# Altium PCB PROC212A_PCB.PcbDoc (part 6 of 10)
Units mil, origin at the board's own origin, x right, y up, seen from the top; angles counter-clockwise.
Board outline 3032.48 x 3598.78 mil, 4 copper layers (Top Layer, L2_GND1, L3_PWR1, Bottom Layer), stack 60.58 mil thick; 432 components, 310 nets, 7775 pads, 1236 vias.
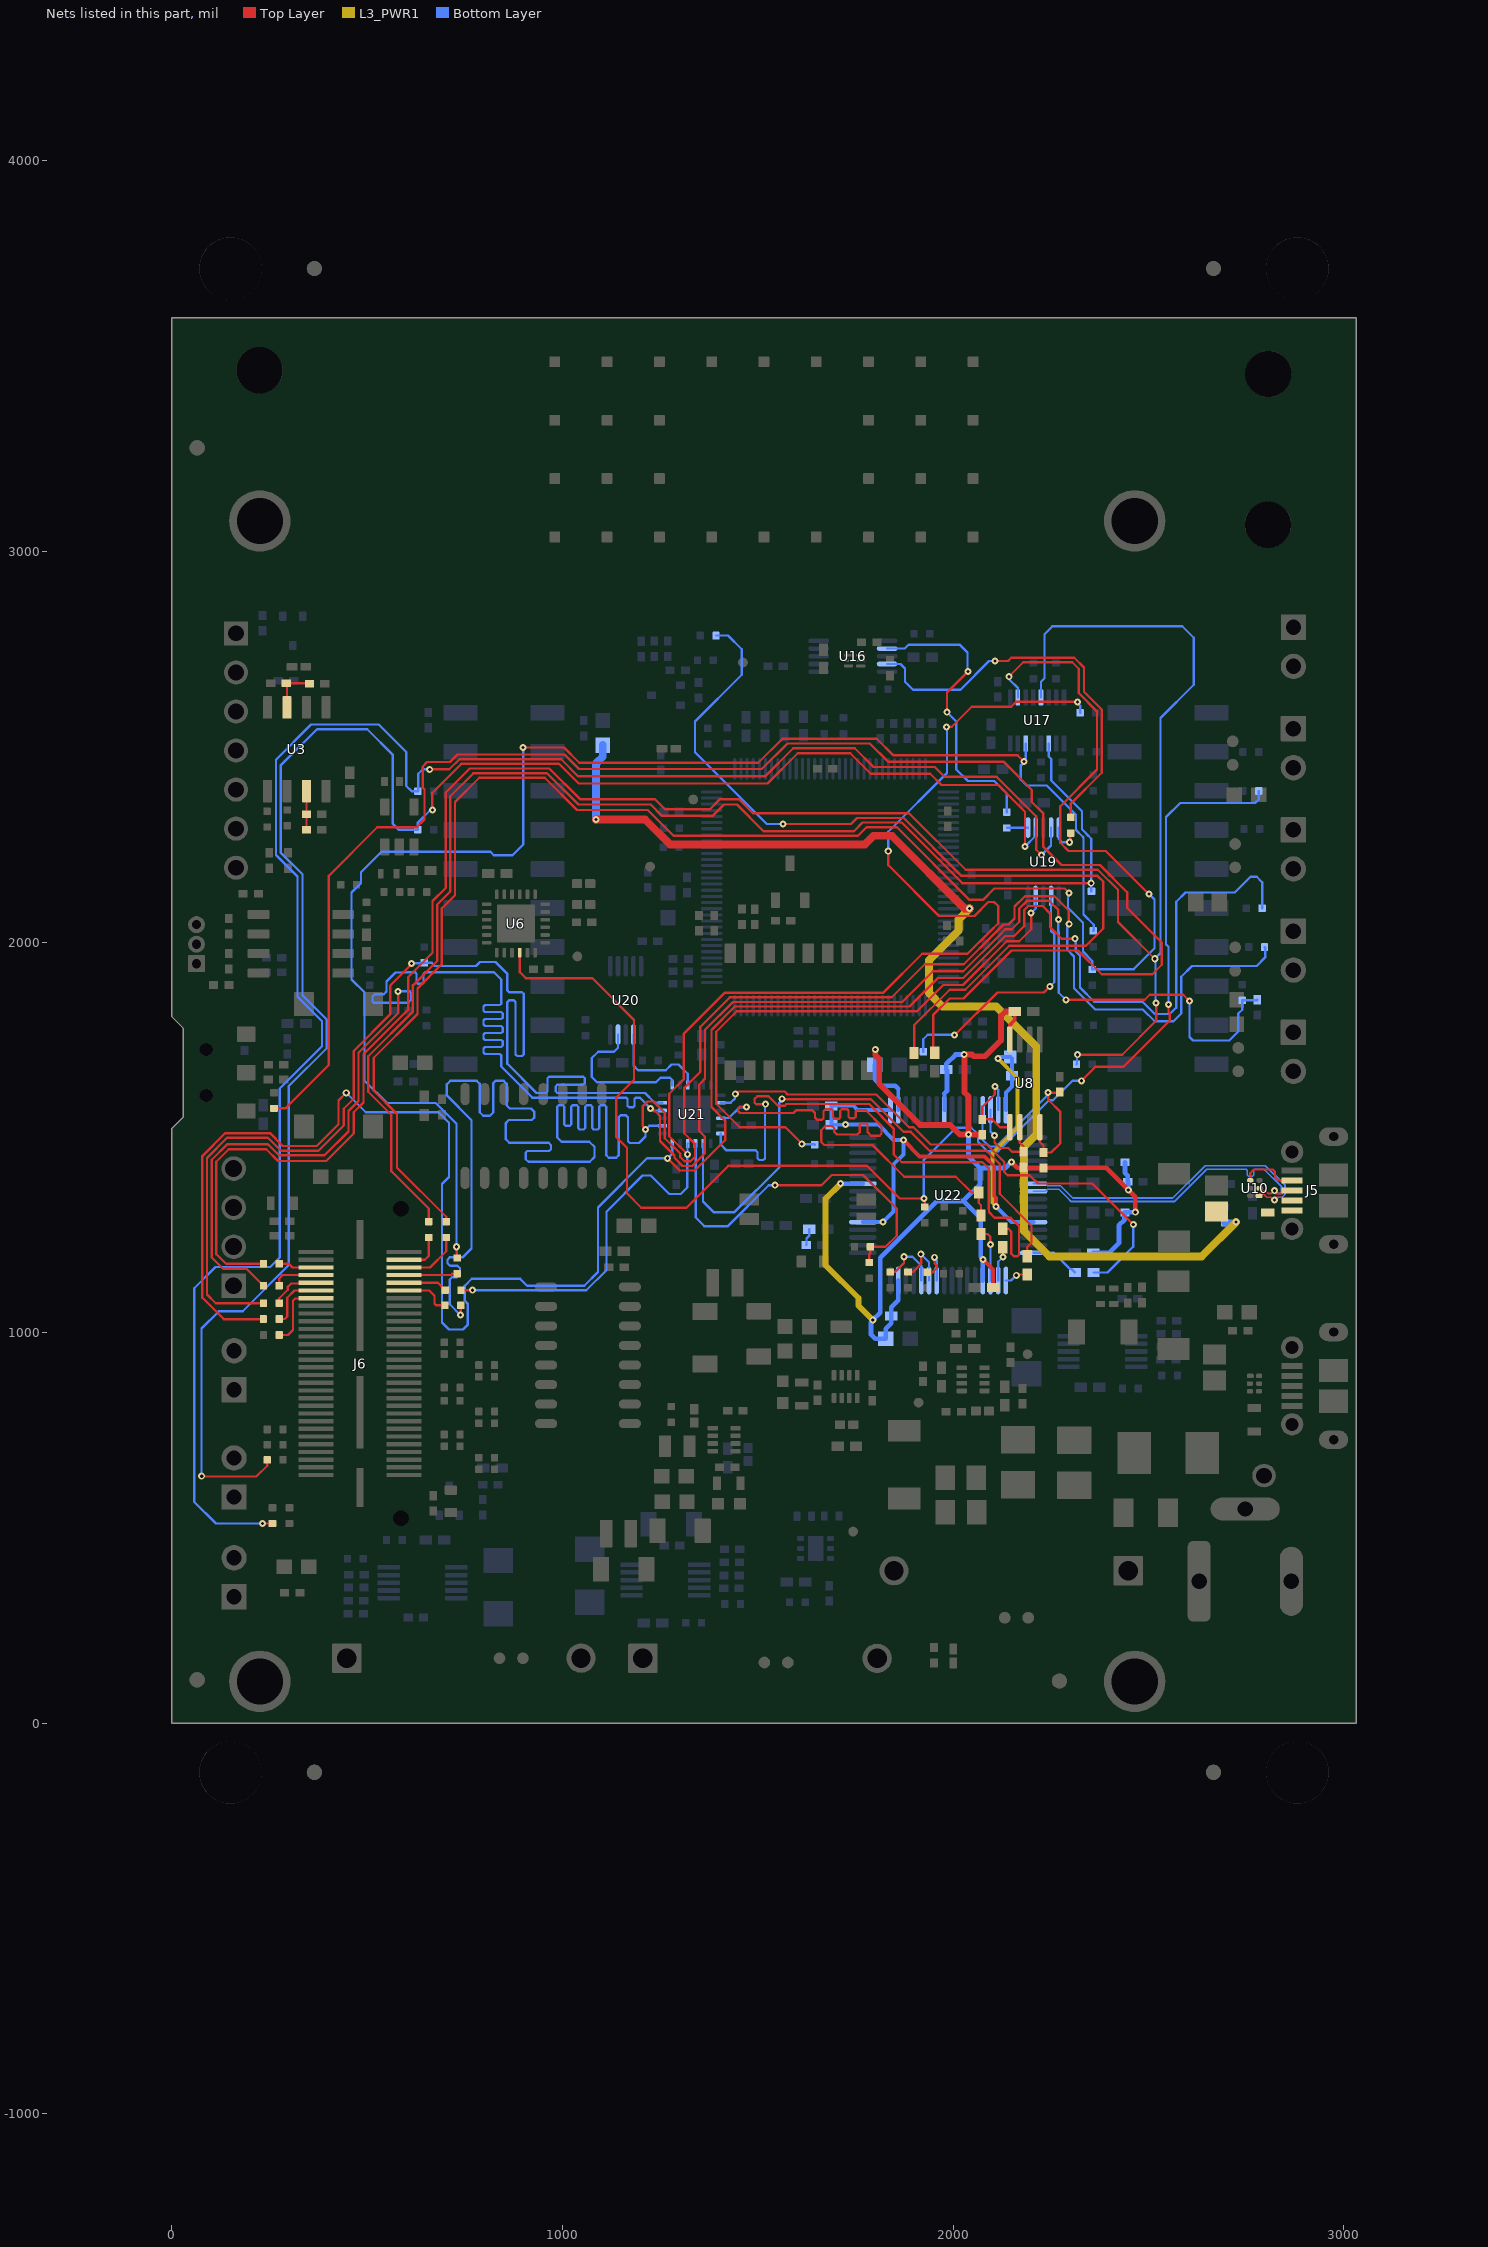
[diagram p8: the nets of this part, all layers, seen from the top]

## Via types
v1: diameter 18, hole 8, Top Layer to Bottom Layer, tented both sides, 1224 vias
v2: diameter 19.68, hole 7.87, Top Layer to Bottom Layer, tented both sides, 10 vias
v3: diameter 19.68, hole 7.87, Top Layer to Bottom Layer, 2 vias

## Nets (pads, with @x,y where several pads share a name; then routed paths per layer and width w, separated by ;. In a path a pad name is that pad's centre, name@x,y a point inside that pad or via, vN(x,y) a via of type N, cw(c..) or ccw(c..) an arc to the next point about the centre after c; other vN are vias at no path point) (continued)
DC_PWM_AUTO_CTRL_GPIO: R40.2 R133.2 U6.16 | length 3484.4
  Top Layer w5.9: U6.16@890.43,1972.62 890.43,1923.12 906.27,1907.27 1076.45,1907.27 1182.87,1800.85 1182.87,1647.28 1137.43,1601.84 1137.43,1500.83 1164.88,1473.38 1164.88,1356.67 1201.55,1319.99 1317.16,1319.99 1424.72,1427.55 1779.55,1427.55 1863.58,1343.52 v1(1925.22,1343.52) 1927.81,1340.93 R40.2@1927.81,1321.6 ; v1(2328.66,1644.86) 2364.23,1680.43 2435.65,1680.43 2555.07,1799.85 2555.07,1818 2551.72,1821.35 v1(2551.72,1840.29)
  Bottom Layer w5.9: v1(1925.22,1343.52) 1925.22,1442.48 2007.64,1524.91 2046.8,1524.91 2063.6,1508.11 2063.6,1489.01 2087.87,1464.74 2115.52,1464.74 2245.63,1594.84 2255.54,1594.84 2305.56,1644.86 v1(2328.66,1644.86) ; v1(2551.72,1840.29) 2551.44,1840.56 2551.44,1988.1 2545.39,1994.15 2545.39,2320.09 2581.4,2356.09 2773.14,2356.09 2782.37,2365.32 R133.2@2782.37,2387.08
DCA_INT: J6.10 R57.1 | length 113.3
  Top Layer w5.9: J6.10@594.31,1127.69 681.28,1127.69 688.86,1120.1 688.86,1119.73 R57.1@699.67,1108.93
DCA_LP_FTDI_SPI_CLK: U20.9 U21.1 | length 392.1
  Bottom Layer w5.9: U20.9@1142.17,1763.23 1142.17,1729.73 1131.77,1719.33 1091.42,1719.33 1075.14,1703.06 1075.14,1654.33 1088.21,1641.25 1216.33,1641.25 1239.62,1641.25 1251.36,1653 1274.7,1653 1281.34,1646.36 U21.1@1281.34,1633.76
DCA_LP_FTDI_SPI_CS: U20.7 U21.3 | length 268.5
  Bottom Layer w5.9: U20.7@1181.54,1763.23 1181.54,1683.86 1193.31,1672.09 1264.29,1672.09 1278.96,1686.77 1296.84,1686.77 1320.71,1662.9 U21.3@1320.71,1633.76
DCA_LP_HOST_INTR_1: R57.2 R111.1 U21.16 | length 3400.9
  Top Layer w5.9: R57.2@740.02,1108.93 769.6,1108.93 v1(769.83,1108.69) ; v1(1319.73,1456.7) 1273.57,1502.86 1273.57,1611.61 1310.04,1648.08 1310.04,1764.52 1416.16,1870.64 1821.85,1870.64 1921.11,1969.89 2037.16,1969.89 2094.21,2026.94 ; v1(1834.06,2232.66) 1834.06,2197.07 1964.13,2067.01 2054.52,2067.01 2090.25,2102.74 2105.12,2102.74 2115.64,2092.23 2115.64,2048.41 2094.21,2026.98 ; v1(1983.31,2551.09) 1983.53,2551.32 1996.53,2551.32 2047.8,2602.58 2149,2602.58 2162.1,2615.68 2317.57,2615.68 v1(2318.53,2614.72)
  Bottom Layer w5.9: v1@770.2,1108.32 1060.75,1108.32 1112.41,1159.99 1112.41,1309.49 1205.12,1402.2 1225.96,1402.2 1273.23,1354.93 1302.48,1354.93 1319.73,1372.18 v1(1319.73,1456.7) 1320.22,1457.19 1320.22,1483.67 U21.16@1320.71,1484.16 ; v1(1834.06,2232.66) 1834.06,2282.68 1984.31,2432.93 1984.31,2550.09 v1(1983.31,2551.09) ; v1(2318.53,2614.72) 2318.53,2611.99 2325.3,2605.23 R111.1@2325.3,2587.21
DCA_LP_SPI_CLK: R58.1 R151.1 U21.23 | length 2907.6
  Top Layer w5.9: R58.1@233.98,1075.22 111.97,1075.22 89.83,1097.36 89.83,1447.53 141.25,1498.95 245.96,1498.95 279,1465.91 375.42,1465.91 439.73,1530.21 439.73,1573.52 465.31,1599.09 465.31,1721.09 558.6,1814.38 558.6,1888.34 613.69,1943.43 v1(613.69,1944.72)
  Bottom Layer w5.9: v1(613.69,1944.72) 614.78,1945.81 644.66,1945.81 R151.1@645.75,1946.9 664.83,1946.9 672.93,1938.79 778.53,1938.79 788.55,1948.81 828.72,1948.81 858.89,1918.64 858.89,1878.83 858.89,1875.88 863.07,1871.7 896.51,1871.7 900.69,1867.52 900.69,1712.39 896.51,1708.21 883.97,1708.21 879.79,1712.39 879.79,1846.62 875.61,1850.8 863.07,1850.8 858.89,1846.62 858.89,1705.26 858.89,1688.33 933.51,1613.7 954.47,1613.7 957.42,1613.7 961.6,1617.88 961.6,1651.32 965.78,1655.5 1052.55,1655.5 1056.73,1651.32 1056.73,1638.78 1052.55,1634.6 986.68,1634.6 982.5,1630.42 982.5,1617.88 986.68,1613.7 1054.47,1613.7 1065.78,1613.7 1210.95,1613.7 1236.17,1588.49 U21.23@1255.75,1588.49
DCA_LP_SPI_CS: R56.1 R158.2 R159.1 U21.22 | length 5473.6
  Top Layer w5.9: R56.1@234.25,1120.2 190.75,1163.7 130.75,1163.7 101.73,1192.72 101.73,1442.6 141.19,1482.05 245.44,1482.05 246.04,1481.46 246.62,1481.46 274.07,1454.01 390.83,1454.01 451.95,1515.12 451.95,1567.73 477.45,1593.24 477.45,1716.41 579.27,1818.23 v1(579.27,1873.83) ; v1(1225.25,1574.11) 1227.35,1574.11 1234.43,1567.03 1237.63,1567.03 1249.77,1554.89 1249.77,1490.62 1286.54,1453.85 1286.54,1447.68 1307.37,1426.85 1332.47,1426.85 1364.31,1458.68 1364.31,1502.09 1349.95,1516.45 1349.95,1635.42 1365.03,1650.51 1365.03,1775.58 1436.29,1846.84 1870.05,1846.84 1948.31,1925.09 2026.02,1925.09 2118.01,2017.08 ; 2118.01,2017.12 2133.87,2032.99 2150.2,2032.99 2169.37,2052.15 2169.37,2085.89 2189,2105.52 2246.02,2105.52 2269.66,2081.88 v1(2269.66,2057.65) ; v1(2289.28,1852.25) 2490.5,1852.25 2503.67,1865.42 2589.22,1865.42 v1(2605.24,1849.4)
  Bottom Layer w5.9: v1(579.27,1873.83) 608.68,1873.83 612.91,1869.6 612.91,1852.47 605.15,1844.71 516.88,1844.71 513.43,1848.16 513.43,1860.56 519.21,1866.34 542.04,1866.34 549.44,1873.75 549.44,1899.39 572.36,1922.31 601.72,1922.31 ; 601.88,1922.15 602.35,1922.62 622.73,1922.62 626.31,1919.04 626.31,1896.6 629.89,1893.02 640.63,1893.02 644.21,1896.6 644.21,1919.04 647.79,1922.62 665.85,1922.62 824.65,1922.62 842.94,1904.33 842.94,1863.24 842.94,1842.38 839.36,1838.8 801.39,1838.8 797.81,1835.22 797.81,1824.48 801.39,1820.9 843.41,1820.9 846.99,1817.32 846.99,1806.58 843.41,1803 801.39,1803 797.81,1799.42 797.81,1788.68 801.39,1785.1 843.41,1785.1 846.99,1781.52 846.99,1770.78 843.41,1767.2 801.39,1767.2 797.81,1763.62 797.81,1752.88 801.39,1749.3 843.41,1749.3 846.99,1745.72 846.99,1734.98 843.41,1731.4 801.39,1731.4 797.81,1727.82 797.81,1717.08 801.39,1713.5 839.36,1713.5 842.94,1709.92 842.94,1701.69 842.94,1681.45 922.58,1601.8 1128.52,1601.8 1162.84,1601.8 1166.42,1598.22 1166.42,1580.64 1170,1577.06 1180.74,1577.06 1184.32,1580.64 1184.32,1598.22 1187.9,1601.8 1190.85,1601.8 1197.55,1601.8 v1(1225.25,1574.11) 1228.52,1574.11 1233.83,1568.8 U21.22@1255.75,1568.8 ; v1(2269.66,2057.65) 2269.66,2026.46 2270.74,2025.38 2270.74,1870.31 v1@2288.8,1852.25 ; v1(2605.24,1849.4) 2605.24,1757.16 2614.31,1748.09 2707.31,1748.09 2730.31,1771.09 2730.31,1817.09 2740.23,1827.01 R158.2@2740.23,1850.76 2776.78,1850.76 R159.1@2778.51,1852.49
DCA_LP_SPI_MISO: R59.2 R150.2 U21.20 | length 5535.5
  Top Layer w5.9: v1(739.08,1044.76) 739.28,1044.96 739.28,1069.66 R59.2@739.48,1069.85 ; v1(1212.69,1520.18) 1212.69,1522.45 1205.7,1529.45 1205.7,1579.6 1207.3,1581.2 1207.3,1581.54 1217.81,1592.06 1233.07,1592.06 1261.67,1563.45 1261.67,1497.93 1301.78,1457.82 1301.78,1449.26 1312.3,1438.75 1327.54,1438.75 1339.31,1450.51 1339.31,1483.25 1311.76,1510.8 1311.76,1626.71 1352.6,1667.55 1352.6,1782.85 1428.49,1858.74 1842.95,1858.74 1927.31,1943.09 2027.19,1943.09 2106.11,2022.01 ; 2106.11,2022.05 2128.94,2044.89 2142.1,2044.89 2157.47,2060.25 2157.47,2090.82 2184.07,2117.42 2259.65,2117.42 2296.56,2080.51 2296.56,2047.33 v1(2297.3,2046.59)
  Bottom Layer w5.9: v1(739.08,1044.76) 711.31,1072.54 711.31,1136.09 716.96,1141.75 729.02,1141.75 737.7,1150.42 737.7,1164.7 731.08,1171.31 711.81,1171.31 705.56,1177.57 705.56,1186.73 712.25,1193.43 745.2,1193.43 767.01,1215.23 767.01,1543.98 703.96,1607.03 703.96,1636.2 712.43,1644.67 780.57,1644.67 788.31,1636.94 788.31,1564.2 797.04,1555.48 814.48,1555.48 822.53,1563.52 822.53,1638.87 828.33,1644.67 849.69,1644.67 856.9,1637.47 856.9,1581.96 864.76,1574.1 919.36,1574.1 927.34,1566.12 927.34,1550.46 921.25,1544.37 862.51,1544.37 855.03,1536.89 855.03,1495 863.87,1486.15 964.5,1486.15 970.55,1480.11 970.55,1469.8 965.74,1464.99 909.96,1464.99 905.9,1460.93 905.9,1444.13 912.71,1437.31 1069.79,1437.31 1081.89,1449.41 1081.89,1475.73 1068.59,1489.04 997.24,1489.04 986.52,1499.76 986.52,1541.93 986.52,1578.64 990.1,1582.22 1000.84,1582.22 1004.42,1578.64 1004.42,1533.34 1008,1529.76 1018.74,1529.76 1022.32,1533.34 1022.32,1578.64 1025.9,1582.22 1036.64,1582.22 1040.22,1578.64 1040.22,1523.93 1043.8,1520.35 1054.54,1520.35 1058.12,1523.93 1058.12,1578.64 1061.7,1582.22 1072.44,1582.22 1076.02,1578.64 1076.02,1523.93 1079.6,1520.35 1090.34,1520.35 1093.92,1523.93 1093.92,1578.64 1097.5,1582.22 1108.24,1582.22 1111.82,1578.64 1111.82,1541.93 1111.82,1454.61 1118.66,1447.77 1137.8,1447.77 1143.64,1453.61 1143.64,1551.49 1148.43,1556.28 1162.49,1556.28 1167.77,1551 1167.77,1490.33 1172.33,1485.77 1196.19,1485.77 1212.69,1502.28 v1(1212.69,1520.18) 1221.95,1529.43 U21.20@1255.75,1529.43 ; v1(2297.3,2046.59) 2297.3,2043.31 2292.41,2038.43 2292.41,1980.53 2309.77,1963.18 2309.77,1881.96 2364.17,1827.56 2485.85,1827.56 2516.28,1797.12 2564.62,1797.12 2584.46,1816.97 2584.46,1911.53 2611.96,1939.02 2777.36,1939.02 2798.99,1960.65 2798.99,1985.42 R150.2@2797.2,1987.21
DCA_LP_SPI_MOSI: R61.1 R147.2 U21.18 | length 5475
  Top Layer w5.9: R61.1@233.89,1034.67 132.78,1034.67 77.93,1089.52 77.93,1452.45 136.32,1510.85 250.89,1510.85 283.93,1477.81 370.49,1477.81 426.54,1533.86 426.54,1594.33 v1(446.31,1614.09) ; v1(1268.59,1446.42) 1300.06,1414.95 1338.6,1414.95 1416.31,1492.65 1416.31,1542.64 1381.46,1577.49 1381.46,1775.17 1441.22,1834.94 1888.15,1834.94 1961.31,1908.09 2026.31,1908.09 2133.86,2015.65 2156.86,2015.65 2181.94,2040.73 2181.94,2081.64 2192.46,2092.15 2229.32,2092.15 2248.25,2073.22 2248.25,2038.63 2278.18,2008.7 v1@2312.19,2008.7
  Bottom Layer w5.9: v1(446.31,1614.09) 496.09,1564.31 682.25,1564.31 709.31,1537.24 709.31,1398.28 691.64,1380.6 691.64,1025.76 709.31,1008.09 745.31,1008.09 757.03,1019.82 757.03,1074.84 749.6,1082.28 749.6,1119.79 767.9,1138.09 891.47,1138.09 909.34,1120.22 1055.82,1120.22 1090.7,1155.11 1090.7,1320.49 1216.63,1446.42 v1(1268.59,1446.42) ; v1@1268.72,1446.29 1281.34,1458.91 U21.18@1281.34,1484.16 ; v1(2312.22,2008.67) 2313.95,2006.94 2313.95,1975.83 2324.95,1964.83 2324.95,1883.61 2361.46,1847.09 2485.23,1847.09 2516.31,1816.01 2555.04,1816.01 2571.28,1832.26 2571.28,2103.07 2595.31,2127.09 2721.31,2127.09 2761.31,2167.09 2777.31,2167.09 2791.31,2153.09 R147.2@2791.29,2086.46
DCA_LP_TCK: R46.2 R156.1 U17.2 | length 4589.4
  Top Layer w5.9: R46.2@702.06,1284.21 702.06,1296.89 576.48,1422.47 576.48,1559.52 516.74,1619.25 516.74,1703.78 628.79,1815.83 628.79,1881.35 691.04,1943.6 691.04,2086.35 724.62,2119.93 724.62,2358.41 786.86,2420.64 954.42,2420.64 1036.97,2338.09 1218.31,2338.09 1284.31,2272.09 1756.31,2272.09 1778.31,2294.09 1856.31,2294.09 2042.28,2108.12 2076.62,2108.12 2105.59,2137.09 2285.7,2137.09 v1(2297.15,2125.64) ; v1(2142.73,2679.43) 2179.6,2716.3 2305.09,2716.3 2321.69,2699.7 2321.69,2637.51 2368.52,2590.67 2368.52,2441.6 2274.38,2347.45 2274.38,2254.11 2295.45,2233.03 2390.65,2233.03 2500.85,2122.83 v1(2501.83,2122.83)
  Bottom Layer w5.9: v1@2145.05,2671.26 2166.01,2650.3 U17.2@2166.01,2626.66 ; v1(2297.15,2125.64) 2294.84,2123.32 2294.84,2116.73 2294.24,2116.13 2294.24,2087.66 2332.44,2049.45 2332.44,1975.72 2356.43,1951.73 R156.1@2356.43,1929.78 2357.01,1930.36 2462.26,1930.36 2515.91,1984.01 2515.91,2108.74 v1(2501.83,2122.83)
DCA_LP_TDI: R49.1 R173.1 U17.5 | length 5711.6
  Top Layer w5.9: R49.1@234.41,1176.28 210.16,1176.28 210.02,1176.42 138.28,1176.42 113.63,1201.07 113.63,1437.67 145.52,1469.56 241.69,1469.56 271.6,1439.65 395.25,1439.65 465.45,1509.85 465.45,1564.24 490.5,1589.29 490.5,1712.63 604.99,1827.12 604.99,1910.64 667.24,1972.89 667.24,2104.98 700.82,2138.56 700.82,2383 762.26,2444.44 966.22,2444.44 1044.57,2366.09 1236.31,2366.09 1262.31,2340.09 1377.31,2340.09 1403.31,2366.09 1451.62,2366.09 1487.62,2330.09 1887.35,2330.09 2032.17,2185.27 2370.71,2185.27 2422.13,2133.85 2422.13,2051.72 v1(2516.47,1957.37) ; v1(2318.31,1711.61) 2432.87,1711.61 2520.26,1799 2520.26,1843.79 v1(2519.91,1844.14)
  Bottom Layer w5.9: U17.5@2225.07,2626.66 2225.07,2666.81 2233.85,2675.6 2233.85,2788.05 2254.22,2808.41 2586.84,2808.41 2616.21,2779.05 2616.21,2658.84 2530.89,2573.52 2530.89,1971.79 v1(2516.47,1957.37) 2518.19,1955.65 2518.19,1845.86 v1(2519.91,1844.14) ; R173.1@2316.14,1687.21 2317.23,1688.3 2317.23,1710.52 v1(2318.31,1711.61)
DCA_LP_TDO: R45.2 R146.1 U17.11 | length 3488.6
  Top Layer w5.9: R45.2@657.27,1284.21 657.27,1317.74 561.38,1413.64 561.38,1557.79 502.4,1616.77 502.4,1707.7 616.89,1822.19 616.89,1889.12 679.14,1951.37 679.14,2095.93 712.72,2129.51 712.72,2373.51 771.76,2432.54 960.41,2432.54 1040.86,2352.09 1225.93,2352.09 1254.93,2323.09 1384.31,2323.09 1413.31,2352.09 1446.8,2352.09 1514.9,2283.99 1746.21,2283.99 1768.21,2305.99 1868.58,2305.99 2023.83,2150.74 v1(2353.63,2150.74)
  Bottom Layer w5.9: U17.11@2244.75,2508.55 2244.75,2475.39 2251.22,2468.93 2251.22,2465.66 2251.22,2413.88 2330.04,2335.05 2330.04,2288.66 2342.58,2276.13 2342.58,2275.72 2353.63,2264.67 v1(2353.63,2150.74) 2353.92,2150.45 2353.92,2130.47 R146.1@2354.21,2130.19
DCA_LP_TMS: R50.2 R148.1 U17.14 | length 3822
  Top Layer w5.9: v1(728.65,1219.92) 729.44,1219.13 R50.2@729.44,1192.04 ; v1(899.31,2498.09) 1003.87,2498.09 1043.04,2458.93 1501.27,2458.93 1562.95,2520.61 1804.79,2520.61 1847.31,2478.09 2165.66,2478.09 v1@2180.9,2462.85
  Bottom Layer w5.9: v1(728.65,1219.92) 728.65,1534.73 675.62,1587.77 550.39,1587.77 492.94,1645.23 492.94,1871.46 459.89,1904.51 459.89,2126.68 483.98,2150.76 483.98,2178.76 536.34,2231.12 815.38,2231.12 824.23,2222.28 871.75,2222.28 899.31,2249.83 v1(899.31,2498.09) ; U17.14@2185.7,2508.55 2185.7,2470.52 2181.3,2466.12 2181.3,2460.07 2173.64,2452.41 2173.64,2415.83 2188.58,2400.9 2239.79,2400.9 2314.81,2325.88 2314.81,2287.07 2332.21,2269.67 2332.21,2269.27 2333.95,2267.53 2333.95,2070.86 2360.46,2044.35 2360.46,2029.96 R148.1@2359.24,2028.74
  other v1: 2181.3,2462.85
DCA_LP_UARTB_RS232_RX: R86.1 R141.1 U19.7 | length 4756.4
  Top Layer w5.9: v1(76.16,632.48) 77.11,631.53 216.12,631.53 244.09,659.5 R86.1@244.09,674.23 ; v1(666.71,2338.58) 666.71,2381.98 741.08,2456.34 991.18,2456.34 1041.43,2406.09 1524.64,2406.09 1602.29,2483.74 1736.54,2483.74 1789.19,2431.09 1941.31,2431.09 1970.31,2402.09 2115.56,2402.09 2125.94,2391.71 2184.02,2333.64 v1(2184.02,2244.39)
  Bottom Layer w5.9: v1(76.16,632.48) 75.75,632.89 75.75,1010.66 120.15,1055.06 181.16,1055.06 299.31,1173.2 299.31,1631.26 396.31,1728.26 396.31,1801.92 334.31,1863.92 334.31,2173.63 278.21,2229.73 278.21,2451.99 371.31,2545.09 499.84,2545.09 565.72,2479.22 565.72,2302.25 580.29,2287.68 R141.1@629.38,2287.68 ; R141.1@629.68,2287.98 629.68,2305.95 660,2336.27 664.4,2336.27 v1(666.71,2338.58) ; v1(2184.02,2244.39) 2184.02,2244.62 2211.51,2272.12 U19.7@2211.51,2293.22
DCA_LP_UARTB_RS232_TX: R89.1 R134.1 U19.9 | length 4860.5
  Top Layer w5.9: v1(231.81,511.23) 232.58,511.23 232.72,511.37 R89.1@257.26,511.37 ; v1(660.01,2442.32) 710.22,2442.32 736.15,2468.24 996.5,2468.24 1040.47,2424.28 1518.49,2424.28 1590.75,2496.54 1748.01,2496.54 1796.45,2448.09 1953.31,2448.09 1977.97,2423.43 2111.47,2423.43 2213.06,2321.84 2213.06,2236.27 v1(2226.58,2222.75)
  Bottom Layer w5.9: v1(231.81,511.23) 215.21,511.23 215.17,511.18 112.52,511.18 57.34,566.36 57.34,1113.85 111.44,1167.95 251.75,1167.95 276.31,1192.51 276.31,1625.09 384.31,1733.09 384.31,1797.09 321.31,1860.09 321.31,2167.63 266.31,2222.63 266.31,2467.09 356.21,2556.99 529.74,2556.99 600.09,2486.65 600.09,2399.93 613.5,2386.52 R134.1@629.68,2386.52 630.83,2387.67 630.83,2431.22 641.93,2442.32 v1(660.01,2442.32) ; v1(2226.58,2222.75) 2250.94,2247.11 U19.9@2250.94,2293.08
DCA_PG: J6.13 R62.2 | length 177
  Top Layer w5.9: R62.2@274.61,993.83 297,993.83 310,1006.82 310,1081.41 315.94,1087.35 367.76,1087.35 J6.13@368.72,1088.32
DCA_SPI_CLK: J6.9 R58.2 | length 127.2
  Top Layer w5.9: R58.2@274.61,1075.49 274.61,1087.96 296.66,1110.01 296.66,1117.17 305.52,1126.03 367.06,1126.03 J6.9@368.72,1127.69
DCA_SPI_CS: J6.7 R56.2 | length 116.1
  Top Layer w5.9: R56.2@274.61,1120.2 274.61,1138.6 283.38,1147.37 J6.7@368.72,1147.37
DCA_SPI_MISO: J6.12 R59.1 | length 132.3
  Top Layer w5.9: J6.12@594.31,1108 658.65,1108 672.22,1094.43 672.22,1074.5 676.88,1069.85 R59.1@699.12,1069.85
DCA_SPI_MOSI: J6.11 R61.2 | length 152.3
  Top Layer w5.9: R61.2@274.61,1035.04 288.58,1035.04 295.18,1041.64 295.18,1089.4 313.79,1108 J6.11@368.72,1108
DCA_TCK: J6.6 R46.1 | length 160.4
  Top Layer w5.9: J6.6@594.31,1167.06 660.85,1167.06 702.06,1208.27 R46.1@702.06,1243.86
DCA_TDI: J6.5 R49.2 | length 97.8
  Top Layer w5.9: R49.2@274.76,1176.28 299.46,1176.28 308.69,1167.06 J6.5@368.72,1167.06
DCA_TDO: J6.4 R45.1 | length 114.4
  Top Layer w5.9: J6.4@594.31,1186.74 647.51,1186.74 657.27,1196.5 R45.1@657.27,1243.86
DCA_TMS: J6.8 R50.1 | length 137.4
  Top Layer w5.9: J6.8@594.31,1147.37 714.2,1147.37 717.72,1150.9 R50.1@730.23,1150.9
EECLK: R34.1 U8.2 U22.62 | length 239.4
  Top Layer w5.9: v1(2106.14,1504.49) 2106.14,1487.04 2120.59,1472.59 2141.11,1472.59 2150.74,1462.96 R34.1@2180.44,1462.96 2180.44,1477.28 2176.68,1481.04 2176.18,1481.04 2170.87,1486.36 U8.2@2170.87,1526.03
  Bottom Layer w5.9: U22.62@2095.81,1570.55 2095.81,1514.81 v1(2106.14,1504.49)
EECS: R33.1 U8.1 U22.63 | length 239.2
  Top Layer w5.9: v1(2107.08,1630.02) 2107.08,1610.41 2074.71,1578.04 R33.1@2074.71,1546.02 2100.26,1546.02 2120.24,1526.03 U8.1@2145.28,1526.03
  Bottom Layer w5.9: v1(2107.08,1630.02) 2115.49,1621.61 U22.63@2115.49,1570.55
EEDATA: R30.1 R35.1 U8.4 U22.61 | length 606.4
  Top Layer w5.9: U8.4@2222.05,1526.03 2222.05,1488.33 2231.41,1478.97 R35.1@2231.41,1461.28 2251.06,1461.28 2274.78,1484.99 2274.78,1565.01 2243.47,1596.32 v1(2243.47,1614.63) 2271.67,1614.63 R30.1@2272.89,1615.85
  Bottom Layer w5.9: U22.61@2076.12,1570.55 2075.5,1569.92 2075.5,1494.17 2088.93,1480.74 2089.09,1480.74 2093.19,1476.64 2110.6,1476.64 2239.3,1605.34 2239.3,1607.19 2243.47,1611.35 v1(2243.47,1614.63)
EEPROM_A2: R3.2 R4.1 U3.3 | length 121.8
  Top Layer w5.9: U3.3@294.65,2601.15 294.65,2660.27 R3.2@292.53,2662.39 351.29,2662.39 R4.1@351.93,2661.75
EEPROM_WPn: R8.1 R10.2 U3.7 | length 99.3
  Top Layer w5.9: R10.2@344.39,2287.35 R8.1@344.39,2327.22 344.65,2327.47 U3.7@344.65,2386.58
FTDI_3V3: C18.1 C27.1 C75.2 C77.1 C89.1 C90.2 L8.1 L9.2 L10.1 R33.2 R34.2 R35.2 R189.1 U8.8 U22.20 U22.31 U22.42 U22.50 U22.56 | length 3692.7
  Top Layer w10: v1(2076.82,1187.24) 2102.69,1161.37 C27.1@2102.69,1115.3 ; U8.8@2145.28,1750.44 2145.28,1788.11 2157.84,1800.67 C18.1@2157.84,1822.34
  Top Layer w12: v1(2149.11,1437.41) 2163.96,1422.56 2176.6,1422.56 2177.52,1421.64 2230.7,1421.64 R35.2@2231.41,1422.35 ; R35.2@2231.49,1421.82 2392.14,1421.82 v1(2448.61,1365.35) 2466.56,1347.41 v1(2466.56,1308.4)
  Top Layer w15: v1@1800.79,1724.05 1800.79,1710.63 1810.96,1700.47 1810.96,1636.62 1915.77,1531.81 1992.82,1531.81 2017.68,1506.96 v1(2039.37,1506.96) ; v1(2028.54,1712.06) 2048.18,1712.06 2052.54,1707.7 2081.86,1707.7 2122.52,1748.35 2122.52,1810.71 2134.14,1822.34 C18.1@2157.84,1822.34 ; v1@2029.43,1711.17 2029.11,1710.85 2029.11,1709.36 2029.43,1709.05 2029.43,1614.87 2039.37,1604.93 v1(2039.37,1506.96) ; R33.2@2074.71,1506.65 2039.68,1506.65 v1(2039.37,1506.96)
  L3_PWR1 w15: v1(1712.23,1381.51) 1673.52,1342.81 1673.52,1172.91 1757.91,1088.52 1757.91,1069.18 v1(1794.49,1032.61)
  Bottom Layer w8: v1(1712.23,1381.51) v1@1712.29,1381.57
  Bottom Layer w10: U22.50@1859.59,1570.55 1859.59,1624.13 ; U22.56@1977.7,1570.55 1977.7,1612.29
  Bottom Layer w12: v1@1712.29,1381.57 U22.42@1769.04,1381.57 ; v1(1800.79,1724.74) 1800.79,1687.08 C75.2@1799.4,1685.69 1799.4,1649.13 1816.54,1631.99 1851.72,1631.99 1859.59,1624.13 ; U22.31@1859.59,1133.54 1859.59,1082.86 1841.53,1064.8 1841.53,1023.72 1827.74,1009.93 C90.2@1827.74,984.52 1800.47,984.52 1789.95,995.04 1789.95,1026.45 1794.49,1030.99 v1(1794.49,1032.61) 1813.38,1051.5 1813.38,1191.43 1959.22,1337.28 2026.43,1337.28 ; 1977.7,1612.29 1984.23,1618.82 1984.23,1672.12 C77.1@1982.45,1673.9 1982.45,1688.21 2006.3,1712.06 v1(2028.54,1712.06) ; v1(2039.37,1506.96) 2039.37,1451.08 2069.07,1421.38 ; U22.20@2076.12,1133.54 2076.12,1186.55 v1(2076.82,1187.24) 2076.82,1188.87 2071.2,1194.49 2071.2,1292.51 2026.43,1337.28 ; v1(2149.11,1437.41) 2133.08,1421.38 2069.07,1421.38 ; R189.1@2358.92,1204.09 2399.31,1204.09 2424.65,1229.43 2424.65,1274.46 2439.03,1288.85 L10.1@2439.03,1307.74 ; L10.1@2440.08,1307.74 2440.42,1308.07 2466.23,1308.07 v1(2466.56,1308.4) ; L8.1@2440.08,1436.22 2440.08,1409.29 2447.15,1402.22 L9.2@2447.15,1386.66 2447.88,1385.93 2447.88,1366.08 v1(2448.61,1365.35) ; 2026.43,1337.28 2069.07,1379.92 2069.07,1421.38
FTDI_12C_SDA_IN: R53.1 U22.27 | length 143.3
  Top Layer w5.9: R53.1@1884.81,1155.51 1897.15,1155.51 1918.6,1176.96 1918.6,1199.56 v1(1917.37,1200.8)
  Bottom Layer w5.9: v1(1917.37,1200.8) 1917.9,1200.8 1938.33,1180.37 U22.27@1938.33,1133.54
FTDI_12C_SDA_OUT: R54.1 U22.28 | length 153
  Top Layer w5.9: R54.1@1838.78,1155.08 1851.13,1155.08 1874.57,1178.52 v1(1874.57,1194.38)
  Bottom Layer w5.9: v1(1874.57,1194.38) 1895.97,1194.38 1918.64,1171.7 U22.28@1918.64,1133.54
FTDI_DCA_LP_RS232_RX_R: R9.1 U19.10 | length 84.9
  Top Layer w5.9: v1(2298.26,2255.61) 2299.94,2257.3 2299.94,2277.25 R9.1@2301.63,2278.94
  Bottom Layer w5.9: U19.10@2270.63,2293.08 2270.63,2264.01 2279.03,2255.61 v1(2298.26,2255.61)
FTDI_DCA_LP_RS232_TX_R: R137.1 U19.6 | length 53.7
  Bottom Layer w5.9: R137.1@2138.16,2293.08 U19.6@2191.89,2293.08
FTDI_DCA_LP_UARTB_RS232_RX: R137.2 U16.7 | length 752.6
  Top Layer w5.9: v1(1984.31,2588.63) 1984.31,2638.96 v1(2037.97,2692.62)
  Bottom Layer w5.9: U16.7@1831.11,2751.47 1876.08,2751.47 1886.31,2761.69 2016.78,2761.69 2037.04,2741.43 2037.04,2693.55 v1(2037.97,2692.62) ; v1(1984.31,2588.63) 2008.31,2564.63 2008.31,2442.1 2038,2412.41 2105.24,2412.41 2137.34,2380.31 R137.2@2137.34,2332.81
FTDI_DCA_LP_UARTB_RS232_TX: R9.2 U16.9 | length 1030.7
  Top Layer w5.9: v1(2107.72,2719.6) 2140.55,2719.6 2149.15,2728.2 2310.02,2728.2 2335.02,2703.2 2335.02,2641.01 2380.42,2595.6 2380.42,2433.76 2301.63,2354.97 R9.2@2301.63,2319.3
  Bottom Layer w5.9: U16.9@1831.11,2712.1 1865.21,2712.1 1877.01,2700.3 1877.01,2666.48 1897.38,2646.11 2018.76,2646.11 2092.24,2719.6 v1(2107.72,2719.6)
FTDI_HOST_INTR_1: R47.2 R51.2 U21.15 | length 993.4
  Top Layer w5.9: v1(1544.18,1377.49) 1597.73,1377.49 1597.83,1377.39 1663.02,1377.39 1689.37,1403.75 1769.7,1403.75 1855.53,1317.92 1855.53,1248.03 1827.18,1219.68 R47.2@1788.19,1219.68 1788.19,1203.42 1785.48,1200.71 R51.2@1785.48,1179.45
  Bottom Layer w5.9: U21.15@1340.4,1484.16 1341.13,1483.42 1341.13,1294.73 1363.07,1272.8 1423.65,1272.8 1528.34,1377.49 v1(1544.18,1377.49)
FTDI_I2C_SCL: R55.1 U22.26 | length 120.5
  Top Layer w5.9: R55.1@1933.91,1154.99 1948.33,1154.99 1958.12,1164.77 1958.12,1172.26 1952.49,1177.88 v1(1952.49,1192.95)
  Bottom Layer w5.9: v1(1952.49,1192.95) 1952.49,1189.68 1958.01,1184.16 U22.26@1958.01,1133.54
FTDI_MISO: R44.1 U22.18 | length 90.4
  Top Layer w5.9: R44.1@2127.33,1218.54 2127.33,1194.4 v1(2127.9,1193.83)
  Bottom Layer w5.9: U22.18@2115.49,1133.54 2115.49,1181.42 v1(2127.9,1193.83)
FTDI_MOSI: R48.1 U22.17 | length 60.8
  Top Layer w5.9: v1(2161.9,1146.83) 2163.72,1148.65 R48.1@2189.75,1148.65
  Bottom Layer w5.9: U22.17@2135.18,1133.54 2148.61,1133.54 v1(2161.9,1146.83)
FTDI_SOP0: R26.2 R32.1 | length 4208
  Top Layer w5.9: R32.1@261.32,1574.17 290.5,1574.2 298.29,1582 401.47,1685.18 401.47,2169.48 525.85,2293.86 626.52,2293.86 646.89,2314.22 646.89,2390.9 642.06,2395.73 642.06,2449.75 653.4,2461.09 712.17,2461.09 731.22,2480.14 1004.99,2480.14 1041.99,2443.15 1510.36,2443.15 1575.92,2508.71 1786.69,2508.71 1833.31,2462.09 2128.96,2462.09 2201.43,2389.62 2201.43,2358.83 2231.26,2329 2231.26,2243.63 2277.56,2197.33 2375.86,2197.33 2445.93,2127.26 2445.93,2087.17 2534.42,1998.68 2534.42,1942.14 2509.89,1917.6 2380.5,1917.6 2319.58,1978.52 2149.42,1978.52 2026.63,1855.73 1991.2,1855.73 1948.95,1813.48 1948.95,1720.26 R26.2@1952.84,1716.37
FTDI_SOP1: R27.2 R98.1 | length 2366.4
  Top Layer w5.9: v1(1564.82,2302.38) 1738.59,2302.38 1754.11,2317.89 1873.51,2317.89 2021.91,2169.49 2369.66,2169.49 2384.36,2154.79 2384.36,2034.67 2340.11,1990.42 2143.63,1990.42 2031.31,1878.09 1991.31,1878.09 1900.73,1787.51 1900.73,1716.54 R27.2@1900.18,1716
  Bottom Layer w5.9: R98.1@1392.94,2784.94 1423.39,2784.94 1458.8,2749.53 1458.8,2684.4 1339.38,2564.98 1339.38,2485.99 1522.99,2302.38 v1(1564.82,2302.38)
FTDI_SPI_CLK: R190.2 U21.8 | length 1415.6
  Top Layer w5.9: v1(1442.35,1611.33) 1445.63,1611.33 1451.53,1617.23 1568.8,1617.23 1576.33,1609.71 1803.28,1609.71 1887.04,1525.94 1898.37,1525.94 1942.64,1481.67 2086.28,1481.67 2131.16,1436.79 2131.16,1411.41 2139.28,1403.29 2195.88,1403.29 2217.26,1381.91 2356.34,1381.91 v1@2461.38,1276.88
  Bottom Layer w5.9: U21.8@1405.36,1588.49 1430.38,1588.49 1441.72,1599.83 1441.72,1610.69 v1(1442.35,1611.33) ; R190.2@2359.62,1154.03 2395.13,1154.03 2461.38,1220.29 v1(2461.38,1276.54)
FTDI_SPI_CS: R36.1 R41.2 U21.10 | length 1403.1
  Top Layer w5.9: v1(1471.53,1578.22) 1453.63,1578.22 1449.33,1573.92 1449.33,1567.2 1454.14,1562.38 1591.6,1562.38 1599.04,1569.83 1638.97,1569.83 1646.44,1562.36 1646.44,1550.6 1651.94,1545.1 1664.44,1545.1 1668.01,1548.67 1668.01,1566.83 1673.16,1571.98 1688.92,1571.98 1692.38,1568.53 1692.38,1551.88 1696.92,1547.34 1707.62,1547.34 1711.08,1550.8 1711.08,1568.15 1715.22,1572.29 1728.68,1572.29 1732.14,1568.84 1732.14,1553.02 1736.36,1548.79 1747.08,1548.79 1750.53,1552.25 1750.53,1566.13 1753.99,1569.59 1776.27,1569.59 1816.96,1528.89 1816.96,1509.05 1812.05,1504.14 1790.39,1504.14 1780.92,1513.61 1780.92,1532.31 1777.47,1535.76 1764.76,1535.76 1761.09,1532.1 1761.09,1513.5 1754.86,1507.26 1702.52,1507.26 1695.75,1514.03 1695.75,1523.47 1689.92,1529.3 1673.47,1529.3 1662.56,1518.39 1662.56,1488.41 1670.34,1480.62 1793.8,1480.62 1875.09,1399.33 2007.09,1399.33 2047.78,1358.64 R36.1@2065.54,1358.64 2065.54,1332.33 2071.58,1326.3 R41.2@2071.58,1299.99 ; R36.1@2071.53,1359.35 R36.1@2071.58,1359.3
  Bottom Layer w5.9: U21.10@1405.74,1549.5 1425.91,1549.5 1453,1576.59 1469.66,1576.59 v1@1471.41,1578.34
FTDI_SPI_MISO: R44.2 U21.12 | length 1449.4
  Top Layer w5.9: v1(1519.51,1584.86) 1496.27,1584.86 1491.59,1589.54 1491.59,1598.41 1498.35,1605.17 1527.34,1605.17 1551.62,1580.89 1569.25,1580.89 1573.6,1585.25 1785.48,1585.25 1847.81,1522.91 1847.81,1456.78 1868.47,1436.12 2075.55,1436.12 2091.36,1420.3 2091.36,1316.25 2091.74,1315.87 2091.74,1308.78 2106.66,1293.86 2147.92,1293.86 2168.63,1273.15 2168.63,1199.68 2164.69,1195.74 2155.66,1195.74 2148.59,1202.81 2148.59,1258.83 2141.64,1265.78 R44.2@2127.33,1265.78
  Bottom Layer w5.9: U21.12@1405.36,1509.75 1405.36,1481.46 1420.11,1466.7 1494.85,1466.7 1499.43,1462.13 1499.43,1446.4 1503.8,1442.02 1514.08,1442.02 1518.27,1446.22 1518.27,1583.62 v1(1519.51,1584.86)
FTDI_SPI_MOSI: R48.2 U21.14 | length 1481.9
  Top Layer w5.9: v1(1561.81,1598.84) 1562.84,1597.81 1789.74,1597.81 1873.51,1514.04 1891.58,1514.04 1939.76,1465.87 2085.26,1465.87 2119.26,1431.86 2119.26,1355.43 2200.88,1273.81 2200.88,1230.44 2189.75,1219.3 R48.2@2189.75,1195.89
  Bottom Layer w5.9: U21.14@1360.08,1484.16 1359.87,1483.95 1359.87,1451.57 1359.66,1451.36 1359.66,1335.83 1386.83,1308.67 1440.32,1308.67 1555.24,1423.59 1555.24,1589.33 1561.81,1595.9 v1(1561.81,1598.84)
FTDI_SPICLK: R190.1 U22.16 | length 127.2
  Bottom Layer w5.9: U22.16@2206.05,1204.4 2257.76,1204.4 2299.27,1162.9 2303.52,1162.9 R190.1@2312.38,1154.03
FTDI_SPICS: R41.1 U22.19 | length 139
  Top Layer w5.9: R41.1@2071.58,1252.75 2088.18,1252.75 2095.57,1245.35 v1(2095.57,1225.58)
  Bottom Layer w5.9: v1(2095.57,1225.58) 2095.69,1225.46 2095.69,1133.66 U22.19@2095.81,1133.54
FTDI_SUSPEND_N: R187.2 R188.1 | length 43.3
  Bottom Layer w5.9: R188.1@1624.16,1224.3 1624.95,1225.1 1624.95,1241.04 1631.43,1247.52 R187.2@1631.43,1264.59
FTDI_UARTB_RS232_RX: R178.2 U19.4 | length 1485.4
  Top Layer w5.9: v1(1612.71,1483.43) 1612.71,1484.01 1593.86,1502.86 1593.8,1502.86 1571,1525.66 1453.64,1525.66 1393.36,1585.94 1393.36,1770.24 1446.15,1823.04 1907.76,1823.04 1974.81,1890.09 2025.14,1890.09 2137.36,2002.32 2169.4,2002.32 2199.89,2032.81 v1(2199.89,2074.2)
  Bottom Layer w5.9: v1(1612.71,1483.43) 1613.74,1482.4 1644.59,1482.4 R178.2@1645.61,1481.37 ; v1(2199.89,2074.2) 2211.57,2085.89 U19.4@2211.57,2117.88
FTDI_UARTB_RS232_TX: R170.2 U19.2 | length 652.1
  Top Layer w5.9: v1(2003.54,1761.78) 2004.36,1761.78 2113.67,1871.09 2232.58,1871.09 v1(2247.6,1886.12)
  Bottom Layer w5.9: R170.2@1923.81,1719.23 1923.81,1751.29 1935.2,1762.68 2002.64,1762.68 v1(2003.54,1761.78) ; v1(2247.6,1886.12) 2258.84,1897.35 2258.84,2020.46 2250.94,2028.35 U19.2@2250.94,2117.88
FTDI_USBD_N: J5.2 U10.1 U22.7 | length 871.9
  Top Layer w4.5: U10.1@2783.63,1350.33 2786.52,1350.33 2790.83,1354.64 2795.62,1354.64 2803.29,1346.96 2813.77,1346.96 2821.27,1339.46 v1(2823.16,1339.46) 2823.16,1344.27 2825.85,1346.96 2841.14,1346.96 J5.2@2843.77,1344.32 ; J5.2@2843.77,1344.29 2849.4,1338.67 J5.2@2868.1,1338.67
  Bottom Layer w4.5: U22.7@2206.05,1381.57 2236.52,1381.57 2241.86,1376.23 2275.02,1376.23 2306.62,1344.63 2562.65,1344.63 2645.51,1427.48 2799.69,1427.48 2850.04,1377.13 2850.04,1354.87 2842.14,1346.96 2832.54,1346.96 2825.04,1339.46 v1(2823.16,1339.46)
FTDI_USBD_P: J5.3 U10.2 U22.8 | length 871.2
  Top Layer w4.5: U10.2@2783.63,1370.01 U10.2@2784.61,1370.01 2785.88,1370.01 2792.25,1363.64 2799.34,1363.64 2807.02,1355.96 2813.77,1355.96 2821.27,1363.46 v1(2823.16,1363.46) 2823.16,1358.65 2825.85,1355.96 2841.14,1355.96 J5.3@2843.77,1358.6 ; J5.3@2843.77,1358.63 2849.4,1364.26 J5.3@2868.1,1364.26
  Bottom Layer w4.5: U22.8@2206.05,1361.89 2236.52,1361.89 2241.86,1367.23 2271.3,1367.23 2284.06,1354.47 2290.42,1348.1 2302.9,1335.63 2566.38,1335.63 2649.24,1418.48 2731.43,1418.48 2750.18,1418.48 2753.48,1415.18 2753.48,1403.78 2756.78,1400.48 2766.68,1400.48 2769.98,1403.78 2769.98,1415.18 2773.28,1418.48 2782.56,1418.48 2795.96,1418.48 2841.04,1373.4 2841.04,1358.6 2838.41,1355.96 2832.54,1355.96 2825.04,1363.46 v1(2823.16,1363.46)
FTDI_USBID: J5.4 U10.4 | length 148.8
  Top Layer w5.9: U10.4@2760.99,1389.7 2760.99,1408.08 2770.67,1417.76 2818.71,1417.76 2824.47,1411.99 2824.47,1398.8 2833.42,1389.85 J5.4@2868.1,1389.85
FTDI_VBUS: C22.2 J5.1 L1.1 R116.1 R185.2 | length 2979.3
  Top Layer w20: v1(1085.56,2313.48) 1211.92,2313.48 1275.31,2250.09 1774.31,2250.09 1796.31,2272.09 1843.31,2272.09 2029.44,2085.96 v1(2042.26,2085.96)
  L3_PWR1 w20: v1(2042.26,2085.96) 2013.77,2057.46 2013.77,2029.05 1938.27,1953.55 1938.27,1869.47 1972.56,1835.18 2110.63,1835.18 2213.11,1732.7 2213.11,1507.54 2181.99,1476.42 2181.99,1259.43 2246.06,1195.36 2636.87,1195.36 v1(2724.67,1283.17)
  Bottom Layer w18: R185.2@2696.11,1281.24 2722.75,1281.24 v1(2724.67,1283.17)
  Bottom Layer w20: v1(1085.56,2313.48) 1085.56,2457.24 1102.94,2474.62 R116.1@1102.94,2504.3
FTDI_VCORE: C74.1 C78.1 C80.1 C81.1 U22.12 U22.37 U22.49 U22.64 | length 1764
  Top Layer w10: v1(1872.7,1493.06) 1914.38,1451.38 2080.01,1451.38 2105.31,1426.08 2105.31,1349.65 2109.54,1345.42 v1(2109.54,1323.46)
  L3_PWR1 w10: v1(2109.54,1323.46) 2109.54,1324.59 2100.78,1333.34 2100.78,1459.85 2165.03,1524.09 2165.03,1651.4 v1(2114.89,1701.54)
  Bottom Layer w10: U22.37@1769.04,1283.14 1769.3,1283.41 1820.45,1283.41 v1(1820.72,1283.68) 1847.69,1310.65 1847.69,1431.18 1872.7,1456.19 v1(1872.7,1493.06) 1872.2,1493.56 1847.69,1493.56 1808.6,1532.66 v1(1724.77,1532.66) 1724.52,1532.4 1688.78,1532.4 C81.1@1688.53,1532.15 1688.37,1532.31 C80.1@1688.37,1580.58 1688.78,1581 1744.81,1581 1755.26,1570.55 U22.49@1839.9,1570.55 ; v1(2109.54,1323.46) 2149.85,1283.14 U22.12@2206.05,1283.14 ; v1@2121.49,1705.99 C74.1@2146.72,1705.99 2150.84,1701.87 C78.1@2150.84,1657.84 2150.84,1630.23 2135.18,1614.57 U22.64@2135.18,1570.55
